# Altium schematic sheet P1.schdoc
size 297 x 209 mm; Symbol: Drawing-Symbol_A4; @Project Name: PGA113AIDGSR; @Page Count: 1; @Update Date: 2026-08-01; @Create Date: 2026-08-01; @Schematic Name: Schematic1; @Page No: 1; @Page Name: P1; Company: EasyEDA.com; Version: V1.0; Page Size: A4; Device: Drawing-Symbol_A4; @Create Time: 18:19:08; @Update Time: 18:19:08; Border: 1; Width: 1170; Height: 825; Region Start: 1; X Region Count: 6; Y Region Count: 4; Blade Width: 10; Title Block Position: 3; @Board Name: Board1
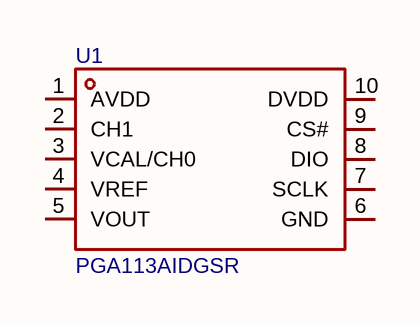
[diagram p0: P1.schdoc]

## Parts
U1  PGA113AIDGSR  [VSSOP-10_L3.0-W3.0-P0.50-LS4.9-BL]

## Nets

Not connected (* = marked no-connect by the designer): U1 1(AVDD) 2(CH1) 3(VCAL/CH0) 4(VREF) 5(VOUT) 6(GND) 7(SCLK) 8(DIO) 9(CS#) 10(DVDD)

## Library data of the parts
U1 = PGA113AIDGSR: Amplifier Type:PGA Number of Channels:2 Rail to Rail:Rail-to-Rail Input；Rail-to-Rail Output Output Current:60mA Current - Supply:1.1mA Operating Temperature:-40℃~+125℃ Operating Temperature:-40℃~+125℃ Vos - Input Offset Voltage:100uV Input Offset Voltage; Manufacturer: TI(德州仪器); AddInBom: yes; ModelId: 3e31ed6b36ca484795e6a68c51b575dc0819f05c4eef4c71ace90d822a990e87; ModelName: VSSOP-10_L3.0-W3.0-H1.1-LS4.9-P0.50; ModelTransform: 197.637,118.11,0,90,0,0,0,0,0; Amplifier Type: PGA; Number of Channels: 2; Output Current: 60mA; Current - Supply: 1.1mA; Vos - Input Offset Voltage: 100uV; Input Offset Voltage Drift(Vos TC): 1.2uV/℃; Ib - Input Bias Current: 5000pA; Input Offset Current(Ios): 5nA; Quiescent Current: 1100000nA; Single Supply: 2.2V~5.5V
